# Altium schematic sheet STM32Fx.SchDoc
size A4; DocumentNumber: 3; Revision: A.1(PCB.SCH); SheetNumber: 3; SheetTotal: 3
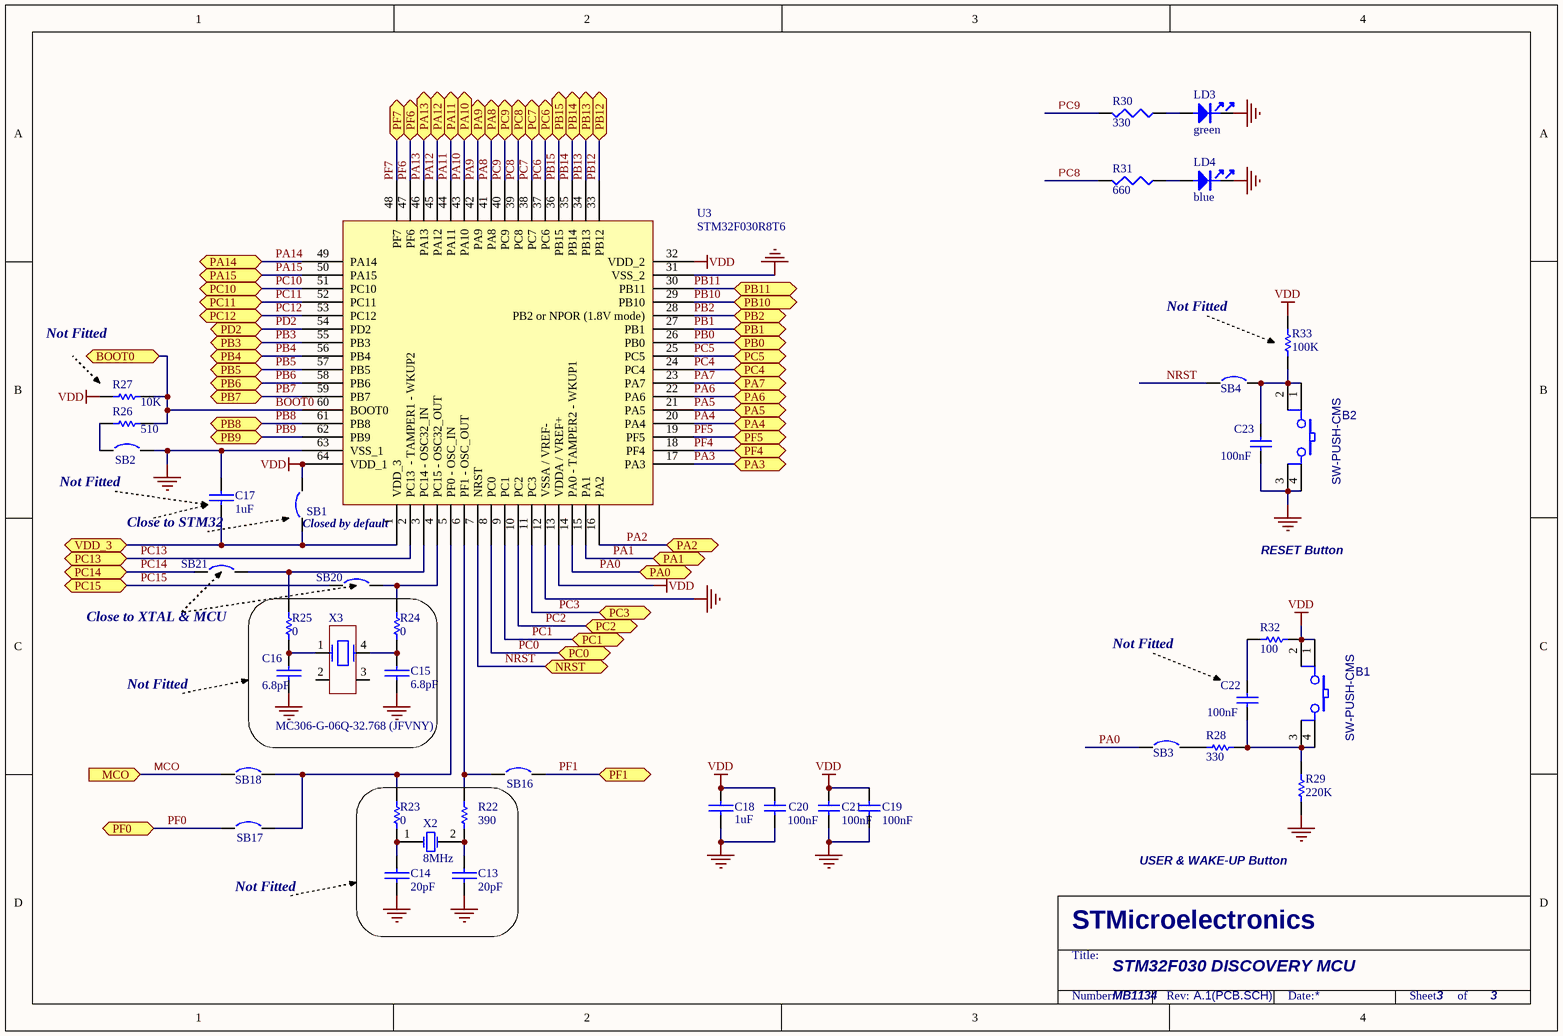
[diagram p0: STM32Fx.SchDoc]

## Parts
B1  SW-PUSH-CMS  [BP1CMS]
B2  SW-PUSH-CMS  [BP1CMS]
C13  20pF  [0603C]
C14  20pF  [0603C]
C15  6.8pF  [0603C]
C16  6.8pF  [0603C]
C17  1uF  [0603C]
C18  1uF  [0603C]
C19  100nF  [0603C]
C20  100nF  [0603C]
C21  100nF  [0603C]
C22  100nF  [0603C]
C23  100nF  [0603C]
LD3  green  [0603D]
LD4  blue  [0603D]
R22  390  [0603R]
R23  0  [0603R-GS]
R24  0  [0603R-GS]
R25  0  [0603R-GS]
R26  510  [0603R]
R27  10K  [0603R]
R28  330  [0402R]
R29  220K  [0603R]
R30  330  [0603R]
R31  660  [0603R]
R32  100  [0402R]
R33  100K  [0402R]
SB1  Circuit Breaker  [JP2_SMD]  (value not drawn)
SB2  Circuit Breaker  [JP2_SMD]  (value not drawn)
SB3  Circuit Breaker  [JP2_SMD]  (value not drawn)
SB4  Circuit Breaker  [JP2_SMD]  (value not drawn)
SB16  Circuit Breaker  [JP2_SMD]  (value not drawn)
SB17  Circuit Breaker  [JP2_SMD]  (value not drawn)
SB18  Circuit Breaker  [JP2_SMD]  (value not drawn)
SB20  Circuit Breaker  [JP2_SMD]  (value not drawn)
SB21  Circuit Breaker  [JP2_SMD]  (value not drawn)
U3  STM32F030R8T6  [LQFP64]
X2  8MHz  [XTAL1]
X3  MC306-G-06Q-32.768 (JFVNY)  [MC306-CRYSTAL]

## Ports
BOOT0, MCO (in), NRST, PA0 (bidir), PA1 (bidir), PA2 (bidir), PA3 (bidir), PA4 (bidir), PA5 (bidir), PA6 (bidir), PA7 (bidir), PA8, PA9, PA10, PA11, PA12, PA13, PA14 (bidir), PA15 (bidir), PB0 (bidir), PB1 (bidir), PB2 (bidir), PB3, PB4 (bidir), PB5 (bidir), PB6 (bidir), PB7 (bidir), PB8 (bidir), PB9 (bidir), PB10 (bidir), PB11 (bidir), PB12 (bidir), PB13 (bidir), PB14 (bidir), PB15 (bidir), PC0 (bidir), PC1 (bidir), PC2 (bidir), PC3 (bidir), PC4 (bidir), PC5 (bidir), PC6 (bidir), PC7 (bidir), PC8 (bidir), PC9 (bidir), PC10 (bidir), PC11 (bidir), PC12 (bidir), PC13 (bidir), PC14 (bidir), PC15 (bidir), PD2, PF0, PF1, PF4, PF5, PF6, PF7, VDD_3

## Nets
GND: B2.3 B2.4 C13.2 C14.2 C15.2 C16.2 C17.1 C18.2 C19.2 C20.2 C21.2 C23.1 LD3.2 LD4.2 R29.1 SB2.2 U3.12(VSSA_/_VREF-) U3.31(VSS_2) U3.63(VSS_1)
VDD: B1.1 B1.2 C18.1 C19.1 C20.1 C21.1 R27.1 R32.2 R33.2 SB1.2 U3.13(VDDA_/_VREF+) U3.32(VDD_2) U3.64(VDD_1)
BOOT0: R26.2 R27.2 U3.60(BOOT0) ; port BOOT0
MCO: SB18.1 ; port MCO
NRST: SB4.1 U3.7(NRST) ; port NRST
PA0: SB3.1 U3.14(PA0_-_TAMPER2_-_WKUP1) ; port PA0
PA1: U3.15(PA1) ; port PA1
PA2: U3.16(PA2) ; port PA2
PA3: U3.17(PA3) ; port PA3
PA4: U3.20(PA4) ; port PA4
PA5: U3.21(PA5) ; port PA5
PA6: U3.22(PA6) ; port PA6
PA7: U3.23(PA7) ; port PA7
PA8: U3.41(PA8) ; port PA8
PA9: U3.42(PA9) ; port PA9
PA10: U3.43(PA10) ; port PA10
PA11: U3.44(PA11) ; port PA11
PA12: U3.45(PA12) ; port PA12
PA13: U3.46(PA13) ; port PA13
PA14: U3.49(PA14) ; port PA14
PA15: U3.50(PA15) ; port PA15
PB0: U3.26(PB0) ; port PB0
PB1: U3.27(PB1) ; port PB1
PB2: U3.28(PB2_or_NPOR_(1.8V_mode)) ; port PB2
PB3: U3.55(PB3) ; port PB3
PB4: U3.56(PB4) ; port PB4
PB5: U3.57(PB5) ; port PB5
PB6: U3.58(PB6) ; port PB6
PB7: U3.59(PB7) ; port PB7
PB8: U3.61(PB8) ; port PB8
PB9: U3.62(PB9) ; port PB9
PB10: U3.29(PB10) ; port PB10
PB11: U3.30(PB11) ; port PB11
PB12: U3.33(PB12) ; port PB12
PB13: U3.34(PB13) ; port PB13
PB14: U3.35(PB14) ; port PB14
PB15: U3.36(PB15) ; port PB15
PC0: U3.8(PC0) ; port PC0
PC1: U3.9(PC1) ; port PC1
PC2: U3.10(PC2) ; port PC2
PC3: U3.11(PC3) ; port PC3
PC4: U3.24(PC4) ; port PC4
PC5: U3.25(PC5) ; port PC5
PC6: U3.37(PC6) ; port PC6
PC7: U3.38(PC7) ; port PC7
PC8: R31.2 U3.39(PC8) ; port PC8
PC9: R30.2 U3.40(PC9) ; port PC9
PC10: U3.51(PC10) ; port PC10
PC11: U3.52(PC11) ; port PC11
PC12: U3.53(PC12) ; port PC12
PC13: U3.2(PC13__-_TAMPER1_-_WKUP2) ; port PC13
PC14: SB21.1 ; port PC14
PC15: SB20.1 ; port PC15
PD2: U3.54(PD2) ; port PD2
PF0: SB17.1 ; port PF0
PF1: SB16.2 ; port PF1
PF4: U3.18(PF4) ; port PF4
PF5: U3.19(PF5) ; port PF5
PF6: U3.47(PF6) ; port PF6
PF7: U3.48(PF7) ; port PF7
VDD_3: C17.2 SB1.1 U3.1(VDD_3) ; port VDD_3
NetB1_3: B1.3 B1.4 C22.1 R28.2 R29.2
NetB2_1: B2.1 B2.2 C23.2 R33.1 SB4.2
NetC13_1: C13.1 R22.2 X2.2(OSC2)
NetC14_1: C14.1 R23.1 X2.1(OSC1)
NetC15_1: C15.1 R24.1 X3.4
NetC16_1: C16.1 R25.1 X3.1
NetC22_2: C22.2 R32.1
NetLD3_1: LD3.1 R30.1
NetLD4_1: LD4.1 R31.1
NetR22_1: R22.1 SB16.1 U3.6(PF1_-_OSC_OUT)
NetR23_2: R23.2 SB17.2 SB18.2 U3.5(PF0_-_OSC_IN)
NetR24_2: R24.2 SB20.2 U3.4(PC15_-_OSC32_OUT)
NetR25_2: R25.2 SB21.2 U3.3(PC14_-_OSC32_IN)
NetR26_1: R26.1 SB2.1
NetR28_1: R28.1 SB3.2

Not connected (* = marked no-connect by the designer): X3 2 3

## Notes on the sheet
- Not Fitted
- (near SB2) Not Fitted
- (near C17) Close to STM32
- (near SB1) Closed by default
- RESET Button
- (near SB21) Close to XTAL & MCU
- (near SB17) Not Fitted
- USER & WAKE-UP Button
- STM32F030 DISCOVERY MCU
- MB1134

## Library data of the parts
B1 B2 = SW-PUSH-CMS: Non-Open Push-Button 0.1A 24V; Manuf_Part_1: TD-0341; Ref St: ********; cap_dec: ---
C13-C17 C22 = CAP: Capacitor; Fitted: NO
C18 C23 = CAP: Capacitor
C19-C21 = Cap: Capacitor; Value: 10nF
LD3 LD4 = PHOTO
R22 = Res1: Resistor; Value: 0; Fitted: NO
R23-R25 = Res1: Resistor; Fitted: NO
R26 = Res1: Resistor
R27 R33 = res1: Resistor; Fitted: NO
R28 = res1: Resistor
R29 = res1: Resistor; Value: 10K
R30 R31 = RES1
R32 = res1: Resistor; Value: 330
SB1-SB4 SB16 SB18 SB20 SB21 = Circuit Breaker: Solder: YES
SB17 = Circuit Breaker: Solder: NO
U3 = STM32F030R8T6: Advanced ARM based 32-bit Cortex M0 MCU with 64 Kbytes Flash and 8 Kbytes of SRAM; Manuf_1: STM; Manuf_Part_1: STM32F051R8T6; Description: Advanced ARM based 32-bit Cortex?M0 MCU with 64 Kbytes Flash and 8 Kbytes of SRAM; Provided: ST
X2 = XTAL: Crystal Oscillator; Fitted: NO
X3 = MC306: Fitted: NO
